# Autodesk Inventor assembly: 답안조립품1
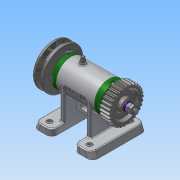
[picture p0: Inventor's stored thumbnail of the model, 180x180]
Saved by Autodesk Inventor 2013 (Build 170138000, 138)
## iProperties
Created: 2016-07
Part Number: 답안조립품1
Document SubType Name: Assembly
Designer: Administrator
Author: Administrator
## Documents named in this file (16)
- C:\Users\Administrator\Desktop\460708V1003\답안조립품1.iam
- C:\Users\Administrator\Desktop\460708V1003\본체.ipt
- C:\Users\Administrator\Desktop\460708V1003\스퍼기어.ipt
- C:\Users\Administrator\Desktop\460708V1003\축.ipt
- C:\Users\Administrator\Desktop\460708V1003\키 3 x 3 x 12.ipt
- C:\Users\Administrator\Desktop\460708V1003\V벨트풀리.ipt
- C:\Users\Administrator\Desktop\460708V1003\너트 M 8.ipt
- C:\Users\Administrator\Desktop\460708V1003\스프링와셔 8.ipt
- C:\Users\Administrator\Desktop\460708V1003\와셔 8x17.ipt
- C:\Users\Administrator\Desktop\460708V1003\오일 실 15 25 7.ipt
- C:\Users\Administrator\Desktop\460708V1003\커버.ipt
- C:\Users\Administrator\Desktop\460708V1003\베어링 15 x 32 x 9.ipt
- C:\Users\Administrator\Desktop\460708V1003\니플 M 6 x 0.75.ipt
- C:\Users\Administrator\Desktop\460708V1003\볼트 M4 x 12.ipt
- C:\Users\Administrator\Desktop\460708V1003\볼트 M 6 x 8.ipt
- C:\Users\Administrator\Desktop\460708V1003\와셔 6x11.5.ipt
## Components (11 placed, 3 different names)
1. V벨트풀리:1
2. KS B 2023 6002 - 15 x 32 x 9:1
3. KS B 2023 6002 - 15 x 32 x 9:2
4. ISO 4762 M4 x 12:2
5. ISO 4762 M4 x 12:3
6. ISO 4762 M4 x 12:4
7. ISO 4762 M4 x 12:5
8. ISO 4762 M4 x 12:1
9. ISO 4762 M4 x 12:6
10. ISO 4762 M4 x 12:7
11. ISO 4762 M4 x 12:8
